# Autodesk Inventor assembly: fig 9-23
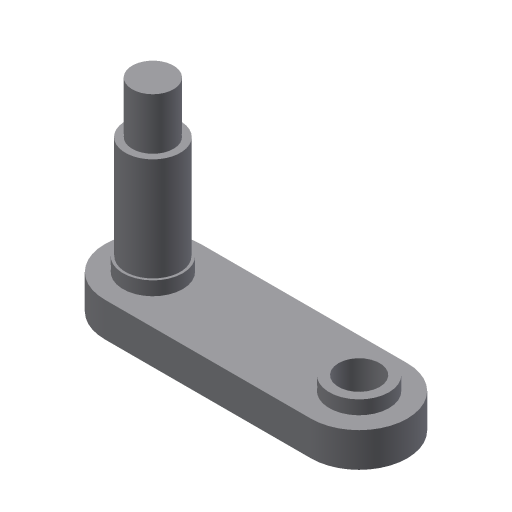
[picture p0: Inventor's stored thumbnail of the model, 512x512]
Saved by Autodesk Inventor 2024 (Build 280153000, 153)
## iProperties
Shininess: 64.0
Length Units: 11269
Angle Units: 11279
Time Units: 11290
Mass Units: 11283
Length Display Precision: 3
Angle Display Precision: 2
Created: 2002-01
Part Number: fig 9-23
Document SubType Name: Assembly
Designer: ***
Density: 0.0
Volumn: 0.0
Area: 0.0
PropertySet Name: Model Information
Control State: 0
Master: False
Checked Out: False
Author: ***
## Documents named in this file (3)
- D:\PROJECTS\Project 2023\RESOURCES INVENTOR 2024\RESOURCES INVENTOR 2024\Inventor_2023_Part\Inventor_2024_Part\c09_Inv_2024_prt\fig 9-23.iam
- D:\PROJECTS\Project 2023\RESOURCES INVENTOR 2024\RESOURCES INVENTOR 2024\Inventor_2023_Part\Inventor_2024_Part\c09_Inv_2024_prt\Part5.ipt
- D:\PROJECTS\Project 2023\RESOURCES INVENTOR 2024\RESOURCES INVENTOR 2024\Inventor_2023_Part\Inventor_2024_Part\c09_Inv_2024_prt\Part6.ipt
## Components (2 placed, 2 different names)
1. Part5:1 — Insert:1
2. Part6:1 — Insert:1
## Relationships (1: Insert 1)
- Insert:1: Part5:1 ↔ Part6:1
